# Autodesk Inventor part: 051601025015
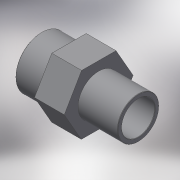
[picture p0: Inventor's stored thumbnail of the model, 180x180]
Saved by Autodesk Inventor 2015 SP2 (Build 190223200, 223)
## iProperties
Created: 2017-10
Part Number: 051601025015
Material: Generic
Description: PLASSON THR. REDUCING NIPPLE 2.1/2"-1.1/2" PVC
Document SubType Name: Modeling
Designer: KIM
Density: 1 g/cm^3
Appearance: Default
Author: KIM
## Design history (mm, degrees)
derived "051601.ipt"
feature "Solid1::051601.ipt"
tag "TaggingFeature1"
body "Solid1"
other parameters: "d0" = 72, "d13" = 0, "d14" = 0.47803, "d17" = 22, "d18" = 36, "d19" = 75.184, "d21" = 47.803, "d23" = 60.1472, "d24" = 38.2424, "d26" = -22, "R_1" = 47.803, "lt_1" = 22, "H_" = 72, "R_" = 75.184
